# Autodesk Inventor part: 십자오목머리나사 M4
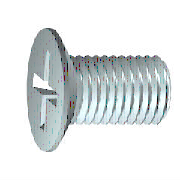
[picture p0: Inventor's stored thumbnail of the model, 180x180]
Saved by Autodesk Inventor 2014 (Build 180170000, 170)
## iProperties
IsCustomPart: 0
Created: 2012-02
Part Number: 십자오목머리나사 M4
Material: 강철, 연강
Description: 십자 오목 머리 나사
Document SubType Name: Modeling
Standard: KS B 1023
Designer: mduedu
Standards Organization: KS
Language: ko-KR
Size Designation: A  M 4 x 12 - H
Categories: <MemberInstance><Categories><Category DisplayName="조임쇠" InternalName="e4da775c-781d-43d5-af7c-5136215cf5a6" Mnemonic="FSTN"><Category DisplayName="볼트" InternalN
Density: 7.86 g/cm^3
Mass: 1.5048 g
Surface Area: 2.78557 cm^2
Volume: 0.191451 cm^3
Appearance: 보라색
Author: mduedu
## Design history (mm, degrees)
body "Solid1"
sketch "스케치1"
  geometry: L1 (2.6, 0)-(12, 0); L2 (12, 0)-(12, 2); L3 (12, 2)-(4.1, 2); L4 (4.1, 2)-(3.671, 1.785); L5 (3.671, 1.785)-(2.7, 1.785); L6 (0, 4.2)-(0, 2.4); L7 (0, 2.4)-(1.801, 1.502); L8 (1.801, 1.502)-(2.6, 0); L9 (-2.4, 0)-(14.4, 0) reference; L10 (0, -0.84)-(0, 5.04) reference; L11 (0, 4.2)-(0.285, 4.2); L12 (0.285, 4.2)-(2.7, 1.785); L13 (4.1, 2)-(2.485, 2)
  constraints: 22 end point, 3 parallel, 3 perpendicular, 2 collinear, 1 horizontal, 1 point on line
  dimensions: "d1" = 7.9 distance of L2.end L3.end (= GEL); "d2" = 4 diameter of L3 L1 (= GD); "d3" = 3.57058 diameter of L5 L1 (= BDM); "d4" = 4.8 diameter of L6.end L1 (= SDM); "d5" = 26.5 deg angle of L7 L1; "d6" = 62 deg angle of L8 L1; "d7" = 2.6 distance from line of L1.start L6 (= INTI); "d8" = 0.42941 horizontal distance of L4.end L3.end (= GAL); "d12" = 8.4 diameter of L11 L1 (= KOD); "d13" = 45 deg angle of L12 L1 (= 0.5 x SEWI); "d15" = 12 distance between parallel lines of L2 L6 (= NLG); "d24" = 2.7 distance from line of L5.end L6 (= KOH)
revolve "본체" stored, may be unused: angle "d16" = 90 deg
sketch "스케치2"
  geometry: L1 (0, 2.4)-(0, 0); L2 (0, 0)-(2.4, 0); L3 (0, 0)-(1.697, 1.697); L4 (0.312, 2.38)-(0.408, 0.734); L5 (2.38, 0.312)-(0.734, 0.408); L6 (0, -5.88)-(0, 5.88) reference; L7 (-5.88, 0)-(5.88, 0) reference; L8 (2.38, -0.312)-(0.734, -0.408); L9 (0.312, -2.38)-(0.408, -0.734); L10 (-0.312, -2.38)-(-0.408, -0.734); L11 (-2.38, -0.312)-(-0.734, -0.408); L12 (-2.38, 0.312)-(-0.734, 0.408); L13 (-0.312, 2.38)-(-0.408, 0.734); A1 r 0.72 centre (0, 0) between (0.72, 0) and (0, 0.72); A2 r 0.84 centre (0, 0) between (0.84, 0) and (0, 0.84); A3 r 2.4 centre (0, 0) between (2.38, 0.312) and (0.312, 2.38); A4 r 2.4 centre (0, 0) between (0.312, 2.38) and (0, 2.4); A5 r 2.4 centre (0, 0) between (2.4, 0) and (2.38, 0.312); A6 r 2.4 centre (0, 0) between (0, -2.4) and (0.312, -2.38); A7 r 2.4 centre (0, 0) between (0.312, -2.38) and (2.38, -0.312); A8 r 2.4 centre (0, 0) between (2.38, -0.312) and (2.4, 0); A9 r 2.4 centre (0, 0) between (0, 2.4) and (-0.312, 2.38); A10 r 2.4 centre (0, 0) between (-0.312, 2.38) and (-2.38, 0.312); A11 r 2.4 centre (0, 0) between (-2.38, 0.312) and (-2.4, 0); A12 r 2.4 centre (0, 0) between (-2.4, 0) and (-2.38, -0.312); A13 r 2.4 centre (0, 0) between (-2.38, -0.312) and (-0.312, -2.38); A14 r 2.4 centre (0, 0) between (-0.312, -2.38) and (0, -2.4); A15 r 0.347 centre (0.755, 0.755) between (0.408, 0.734) and (0.734, 0.408); A16 r 0.347 centre (0.755, -0.755) between (0.734, -0.408) and (0.408, -0.734); A17 r 0.347 centre (-0.755, -0.755) between (-0.408, -0.734) and (-0.734, -0.408); A18 r 0.347 centre (-0.755, 0.755) between (-0.734, 0.408) and (-0.408, 0.734); 3 further points
  constraints: 41 point on circle, 22 end point, 22 symmetric about line, 18 centre point, 11 coincident, 4 point on line, 3 tangent, 2 collinear, 1 perpendicular, 1 vertical, 19 other
  dimensions: "d17" = 1.44 diameter of A1 (= 0.3 x SDM); "d18" = 1.68 diameter of A2 (= 0.35 x SDM); "d19" = 4.8 diameter of A3 (= SDM); "d20" = 45 deg angle of L3 L2; "d21" = 0.3115 distance from line of L4.start L1 (= 0.5 x SBR)
extrude "슬롯" join sketch "스케치2" taper "d22" = 5 deg; stored distance "d79" = 25.4
fillet "모깎기1" dims "d23" = 0.1246 (= 0.2 x SBR)
feature "스레드" dims "d10" = 7.9 (= GEL), "d11" = 0
chamfer "모따기1" distance "d25" = 0.42941 (= -0.5 x SPD + 0.5 x GD); stored, may be unused: second distance "d26" = 0.21471 (= 0.5 x GAL), angle "d88" = 45 deg
workplane "Work Plane2"
other parameters: "NLG" = 12 [user parameter; used in 1 equation term], "GEL" = 7.9 [user parameter; used in 2 equation terms], "GAL" = 0.42941 (= 0.61345 x PTC) [user parameter; used in 3 equation terms], "SPD" = 3.14117 (= NND - 1.2269 x PTC) [user parameter; used in 1 equation term], "KOD" = 8.4 [user parameter; used in 1 equation term], "KOH" = 2.7 [user parameter; used in 1 equation term], "SBR" = 0.623 [user parameter; used in 2 equation terms], "INTI" = 2.6 [user parameter; used in 1 equation term], "SDM" = 4.8 [user parameter; used in 5 equation terms], "GD" = 4 (= NND) [user parameter; used in 2 equation terms], "BDM" = 3.57058 (= NND - GAL) [user parameter; used in 1 equation term], "SEWI" = 90 deg [user parameter; used in 1 equation term], "d9" = 4.8 (= SDM), "d27" = 0, "d91" = 0, "d92" = 0, "GUL" = 0.42941 (= 0.61345 x PTC) [user parameter], "TOA" = 30 deg [user parameter], "EPV" = 4.7 [user parameter], "THREADDIA" = 4 [user parameter; used in 1 equation term], "TPU" = 14.28571 (computed from PTC) [user parameter], "PTC" = 0.7 [user parameter; used in 5 equation terms], "NND" = 4 [user parameter; used in 3 equation terms], "GD1" = 3.14117 (= THREADDIA - 1.2269 x PTC) [user parameter]
